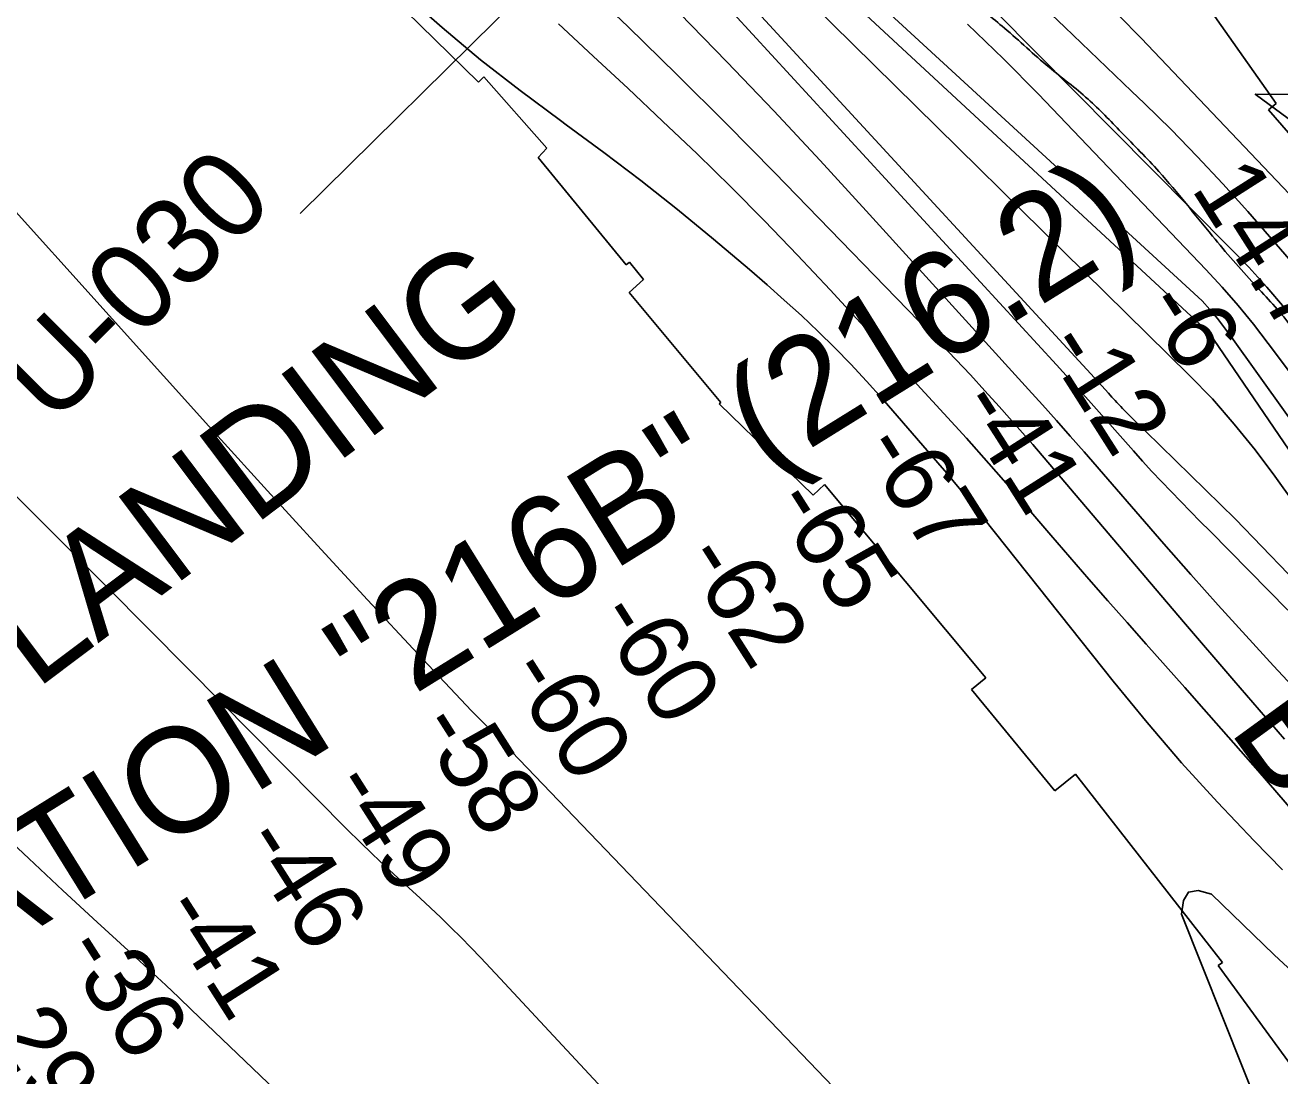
# Model space of a CAD drawing. Extents: x 3329297 to 3367176, y 649250 to 674653.
# Drawn here: x 3339953 to 3341150, y 667351 to 668353 of the extents above; entities that cross this region are included whole.
import ezdxf

# ---------------------------------------------------------------- set-up
doc = ezdxf.new("R2010")
doc.units = 0
for name, color, linetype in [('V-CHAN-NAID', 7, 'Continuous'), ('V-RIVR-EDGE', 7, 'Continuous'), ('V-RIVR-RANG', 7, 'Continuous'), ('V-RIVR-RANG-IDEN', 7, 'Continuous'), ('V-RRAP-RVMT', 7, 'Continuous'), ('V-RRAP-RVMT-IDEN', 7, 'Continuous'), ('V-TOPO-DPTH', 7, 'Continuous'), ('V-TOPO-GNAM-IDEN', 7, 'Continuous'), ('V-TOPO-MAJR', 7, 'Continuous'), ('V-TOPO-MINR', 7, 'Continuous'), ('V-TOPO-WATR', 7, 'Continuous')]:
    doc.layers.add(name, color=color, linetype=linetype)

msp = doc.modelspace()

# ---------------------------------------------------------------- linework, layer by layer
at = {"layer": 'V-CHAN-NAID'}
msp.add_lwpolyline([(3341203.1, 668286.4), (3341126.6, 668286.9), (3341188.2, 668241.5)], dxfattribs=at)
at = {"layer": 'V-RIVR-EDGE'}
msp.add_spline([(3342816.4, 664076.7), (3342812.8, 664100.7), (3342811.2, 664114.7), (3342810.5, 664125.2), (3342811.7, 664129.4), (3342815.9, 664131.4), (3342822.1, 664131), (3342827.6, 664133.7), (3342828, 664138.7), (3342825.7, 664163.5), (3342823, 664169.3), (3342818, 664185.3), (3342816.5, 664200), (3342816.9, 664208.9), (3342818.1, 664220.9), (3342817.3, 664227.1), (3342814.7, 664243.4), (3342809.3, 664257.4), (3342808.5, 664264), (3342808.9, 664272.5), (3342814.8, 664296.2), (3342814.8, 664305.5), (3342810.6, 664319.5), (3342799.8, 664338.9), (3342790.9, 664350.1), (3342779.7, 664360.3), (3342778.5, 664365.3), (3342779.3, 664369.2), (3342779.7, 664370.7), (3342785.9, 664376.9), (3342798.3, 664388.1), (3342804.2, 664396.3), (3342807.7, 664410.2), (3342807.3, 664416.8), (3342805, 664421.5), (3342805, 664424.2), (3342805.1, 664435), (3342805.5, 664451.3), (3342803.6, 664468.4), (3342800.1, 664485.5), (3342800.2, 664492.1), (3342800.6, 664495.9), (3342805.6, 664499.4), (3342810.3, 664507.2), (3342811.5, 664513.7), (3342812.6, 664526.5), (3342808.8, 664554.1), (3342808.5, 664564.6), (3342812, 664571.5), (3342819.8, 664577.7), (3342825.2, 664588.6), (3342825.6, 664596.7), (3342825.3, 664604.1), (3342821.4, 664610.7), (3342817.5, 664623.9), (3342808.6, 664632), (3342807.5, 664639), (3342807.5, 664645.6), (3342805.6, 664651), (3342795.5, 664667.7), (3342786.3, 664683.3), (3342782.8, 664682.1), (3342779.3, 664685.6), (3342772.4, 664698.8), (3342765, 664705.8), (3342757.7, 664715.1), (3342755, 664721), (3342755, 664725.2), (3342756.9, 664729.5), (3342762.4, 664734.9), (3342763.2, 664745.8), (3342759.3, 664768.7), (3342756.7, 664780.7), (3342750.5, 664796.2), (3342738.9, 664818.3), (3342728.9, 664839.3), (3342718.8, 664850.6), (3342704.5, 664870.4), (3342673.2, 664906.9), (3342667, 664917), (3342662.4, 664928.7), (3342645.8, 664948.1), (3342638.8, 664957.4), (3342632.6, 664969.9), (3342630.7, 664978), (3342626.9, 664985), (3342614.9, 664996.7), (3342611.4, 664999.4), (3342609.8, 665001.3), (3342609.9, 665006.4), (3342606.8, 665010.2), (3342597.9, 665020.4), (3342593.2, 665025.4), (3342592.5, 665033.2), (3342590.9, 665044.4), (3342589.4, 665054.5), (3342588.3, 665065.4), (3342586, 665077), (3342585.2, 665086.7), (3342585.3, 665096.4), (3342584.9, 665101), (3342582.9, 665104.2), (3342580.2, 665109.6), (3342577.2, 665117), (3342577.2, 665122.8), (3342577.2, 665131.7), (3342577.2, 665142.6), (3342577.3, 665154.2), (3342576.1, 665167.8), (3342572.7, 665193), (3342566.9, 665215.1), (3342563.5, 665229.5), (3342558.9, 665239.9), (3342557.3, 665244.2), (3342555.4, 665255.5), (3342553.1, 665268.7), (3342549.3, 665284.6), (3342541.6, 665307.1), (3342537.3, 665321.8), (3342532, 665340.1), (3342533.5, 665343.6), (3342533.5, 665349.8), (3342527, 665368.4), (3342525.5, 665379.6), (3342523.5, 665388.2), (3342518.1, 665403.7), (3342515.5, 665416.1), (3342514.3, 665430.9), (3342508.6, 665450.6), (3342503.2, 665470.8), (3342492.4, 665490.6), (3342491.6, 665499.2), (3342490.9, 665508.5), (3342486.3, 665532.9), (3342483.6, 665545.3), (3342477.8, 665557.8), (3342475.9, 665580.3), (3342474.8, 665594.2), (3342470.2, 665605.5), (3342467.9, 665614.4), (3342467.1, 665629.5), (3342466.4, 665643.5), (3342466.8, 665662.1), (3342467.3, 665679.6), (3342463.4, 665695.5), (3342454.9, 665713.7), (3342445.7, 665732.3), (3342448.4, 665735.4), (3342449.6, 665735.1), (3342454.6, 665728.8), (3342456.1, 665730.4), (3342456.1, 665730.8), (3342455.4, 665734.7), (3342442.2, 665751), (3342428.7, 665771.6), (3342413.6, 665800.7), (3342398.6, 665832.5), (3342380.5, 665869.4), (3342358.9, 665914.1), (3342350, 665938.5), (3342337.3, 665963.4), (3342312.2, 666021.6), (3342297.2, 666058.5), (3342281.7, 666092.6), (3342274.8, 666112.4), (3342267.5, 666136.1), (3342262.9, 666166), (3342261.4, 666190.8), (3342261.4, 666198.6), (3342257.6, 666197.8), (3342255.2, 666199.7), (3342252.9, 666205.2), (3342252.6, 666212.5), (3342252.6, 666219.1), (3342250.3, 666232.7), (3342241.8, 666258.3), (3342236.1, 666285.9), (3342231.8, 666289), (3342227.6, 666291.7), (3342219, 666302.6), (3342218.7, 666306.9), (3342219.1, 666312.3), (3342210.2, 666314.2), (3342205.1, 666318.9), (3342204, 666324.3), (3342204, 666330.2), (3342202.1, 666339.1), (3342191.6, 666356.6), (3342180, 666369), (3342175.4, 666377.5), (3342165, 666397), (3342154.6, 666421.8), (3342139.9, 666463.3), (3342130.7, 666487.8), (3342123, 666506.4), (3342111.8, 666527.4), (3342098.7, 666554.2), (3342094.8, 666565.8), (3342092.5, 666581.7), (3342088.7, 666594.5), (3342085.2, 666612.8), (3342082.2, 666622.1), (3342072.9, 666631.8), (3342063.2, 666645.4), (3342057.4, 666657.8), (3342049.7, 666678), (3342048.2, 666693.1), (3342050.2, 666696.6), (3342051, 666704.4), (3342046.7, 666709), (3342039.4, 666716.8), (3342032.4, 666729.2), (3342015.8, 666761.1), (3342003.1, 666780.9), (3341996.1, 666786.3), (3341994.9, 666792.6), (3341992.6, 666796.4), (3341983, 666812), (3341967.1, 666835.3), (3341953.6, 666848.9), (3341946.6, 666857.4), (3341940.5, 666867.9), (3341935.8, 666874.1), (3341919.2, 666884.3), (3341915.7, 666890.1), (3341911.4, 666900.2), (3341899.8, 666913.8), (3341894.8, 666921.2), (3341889, 666931.6), (3341869.3, 666956.9), (3341855, 666974.8), (3341848.8, 666978.7), (3341839.5, 666986.8), (3341829.1, 667000.4), (3341821.8, 667015.2), (3341819.1, 667024.9), (3341817.1, 667031.1), (3341806.3, 667038.9), (3341788.1, 667056.8), (3341778.5, 667070), (3341769.6, 667076.2), (3341763, 667079.7), (3341756, 667089), (3341748.3, 667099.5), (3341738.6, 667112.3), (3341730.9, 667120.1), (3341719.3, 667133.7), (3341714.7, 667143), (3341706.5, 667156.6), (3341694.9, 667171.8), (3341682.2, 667199), (3341673.7, 667217.2), (3341665.7, 667244.8), (3341658.4, 667270.8), (3341654.5, 667280.9), (3341646.8, 667297.6), (3341633.7, 667325.5), (3341621.3, 667347.3), (3341603.9, 667370.6), (3341601.6, 667379.1), (3341595.1, 667392.3), (3341586.6, 667412.5), (3341578.1, 667435.8), (3341568.4, 667448.2), (3341554.1, 667467.6), (3341537.5, 667492.5), (3341516.7, 667524), (3341476.1, 667581.9), (3341429.7, 667650.2), (3341398, 667697.2), (3341371, 667737.2), (3341354.8, 667763.6), (3341343.5, 667778.4), (3341338.9, 667782.3), (3341332.3, 667790.1), (3341325.4, 667806), (3341317.7, 667814.2), (3341305.3, 667827.4), (3341300.6, 667833.2), (3341282.9, 667869.7), (3341259.7, 667911.2), (3341224.6, 667969.5), (3341190.6, 668018.4), (3341159.7, 668067), (3341126, 668105.5), (3341085.8, 668151.7), (3341034.8, 668213.1), (3340998.8, 668250.8), (3340967.1, 668282.3), (3340929.9, 668312.7), (3340887.4, 668350), (3340852.5, 668378), (3340818.1, 668406), (3340783.6, 668439.1), (3340747.7, 668476), (3340722.9, 668504.4), (3340704.4, 668525.7), (3340693.9, 668537), (3340680.7, 668543.2), (3340672.6, 668546.8), (3340664.5, 668552.6), (3340650.9, 668563.5), (3340645.9, 668568.9), (3340640.9, 668576.7), (3340634.7, 668584.1), (3340619.6, 668601.6), (3340609.5, 668604.7), (3340603.7, 668609), (3340599.1, 668614.4), (3340595.6, 668621), (3340589.4, 668627.2), (3340567.8, 668645.9), (3340550, 668659.1), (3340496.9, 668702.7), (3340430.8, 668760.6), (3340383.9, 668798.8), (3340346.8, 668824.5), (3340317, 668845.1), (3340289.9, 668863.4), (3340255.4, 668891.8), (3340209.4, 668936.1), (3340181.1, 668962.9), (3340159.1, 668977.3), (3340134.3, 668996.4), (3340120.7, 669009.2), (3340113.4, 669017.8), (3340109.9, 669023.6), (3340107.6, 669025.9), (3340099.8, 669026.7), (3340094.4, 669027.9), (3340089.4, 669030.2), (3340085.1, 669036.5), (3340084.8, 669043), (3340082.1, 669046.2), (3340066.2, 669059), (3340051.1, 669071.4), (3340041.8, 669077.7), (3339987.6, 669116.2), (3339929.5, 669149.3), (3339882.3, 669177.3), (3339823.8, 669212), (3339768.8, 669245.9), (3339704.9, 669289.5), (3339659.6, 669320.6), (3339614, 669359.5), (3339576, 669382.9), (3339562.9, 669393), (3339559.4, 669394.5), (3339555.9, 669394.2), (3339553.2, 669389.9), (3339550.8, 669388.7), (3339546.2, 669392.2), (3339540.4, 669395.4), (3339537.3, 669393), (3339533, 669392.7), (3339518.7, 669398.1), (3339507.8, 669404.7), (3339498.9, 669411.4), (3339490, 669411.4), (3339486.5, 669416), (3339483.4, 669417.6), (3339473.4, 669420.7), (3339460.6, 669427.7), (3339447.8, 669435.5), (3339435.4, 669443.3), (3339423.8, 669453.4), (3339413.4, 669464.7), (3339407.9, 669471.3), (3339393.6, 669479.5), (3339378.1, 669489.2), (3339357.6, 669502.4), (3339355.7, 669504.8), (3339358.4, 669506.3), (3339359.6, 669509.4), (3339359.2, 669511), (3339356.5, 669515.3), (3339347.2, 669516.8), (3339341.3, 669512.6), (3339338.2, 669513.4), (3339320.8, 669525.8), (3339311.2, 669534.8), (3339296.1, 669548.8), (3339293.3, 669550.3), (3339286.4, 669549.2), (3339280.9, 669546.5), (3339277.1, 669546.5), (3339268.1, 669550), (3339250.7, 669559.7), (3339229, 669575.7), (3339210.8, 669587), (3339202.3, 669595.1), (3339200.4, 669599.4), (3339200, 669604.8), (3339198.1, 669611), (3339183, 669622.7), (3339166.4, 669632.4)], degree=3, dxfattribs=at)
at = {"layer": 'V-RIVR-RANG'}
msp.add_line((3341169.4, 669114.2), (3340215.5, 668173.1), dxfattribs=at)
at = {"layer": 'V-RRAP-RVMT'}
for p, q in [((3340297.9, 668384.3), (3340385.5, 668298.4)), ((3341146.5, 668278.1), (3341084.1, 668366.6)), ((3340385.5, 668298.4), (3340390.9, 668303.4)), ((3340390.9, 668303.4), (3340450.9, 668235.5)), ((3341139.4, 668272.1), (3341146.5, 668278.1)), ((3341224.3, 668173.5), (3341139.4, 668272.1)), ((3340450.9, 668235.5), (3340442.5, 668226.5)), ((3340442.5, 668226.5), (3340526.4, 668124.2)), ((3340526.4, 668124.2), (3340529.7, 668126.9)), ((3340529.7, 668126.9), (3340543.2, 668110.2)), ((3340543.2, 668110.2), (3340529.4, 668097.9)), ((3340529.4, 668097.9), (3340616.7, 667993.1)), ((3340616.7, 667993.1), (3340615.3, 667991.8)), ((3340615.3, 667991.8), (3340704.9, 667904.5)), ((3340704.9, 667904.5), (3340715.7, 667914.8)), ((3340715.7, 667914.8), (3340869.7, 667730.2)), ((3340869.7, 667730.2), (3340856.1, 667719.2)), ((3340856.1, 667719.2), (3340935.6, 667622.6)), ((3340935.6, 667622.6), (3340955.1, 667638.6)), ((3340955.1, 667638.6), (3341095.3, 667459)), ((3341095.3, 667459), (3341091.3, 667456.1)), ((3341091.3, 667456.1), (3341167.1, 667352))]:
    msp.add_line(p, q, dxfattribs=at)
at = {"layer": 'V-TOPO-DPTH'}
for points in [[(3341163.7, 667897), (3341145.4, 667922.7), (3341126.4, 667947.9), (3341106.5, 667972.4), (3341086, 667996.4), (3341063.9, 668018.6), (3340301.5, 668769.4)], [(3341163.7, 667897), (3341145.4, 667922.7), (3341126.4, 667947.9), (3341106.5, 667972.4), (3341086, 667996.4), (3341063.9, 668018.6), (3340301.5, 668769.4)], [(3340336.2, 668769.9), (3341076.1, 668089.9), (3341083.4, 668081.6), (3341090.6, 668073.1), (3341097.4, 668064.3), (3341104.1, 668055.4), (3341257.6, 667840.6)], [(3341257.6, 667840.6), (3341104.1, 668055.4), (3341097.4, 668064.3), (3341090.6, 668073.1), (3341083.4, 668081.6), (3341076.1, 668089.9), (3340336.2, 668769.9)], [(3340520.1, 668482.6), (3340936.9, 668028.8), (3340952.2, 668012), (3340967.5, 667995.1), (3340982.7, 667978.1), (3340997.8, 667961.1), (3341010.4, 667946.8), (3341019.2, 667936.9), (3341028.1, 667927.2), (3341037.2, 667917.5), (3341046.4, 667908), (3341055.7, 667898.5), (3341064.9, 667889.1), (3341074.2, 667879.6), (3341083.5, 667870.2), (3341157.8, 667794.8)], [(3341157.8, 667794.8), (3341083.5, 667870.2), (3341074.2, 667879.6), (3341064.9, 667889.1), (3341055.7, 667898.5), (3341046.4, 667908), (3341037.2, 667917.5), (3341028.1, 667927.2), (3341019.2, 667936.9), (3341010.4, 667946.8), (3340997.8, 667961.1), (3340982.7, 667978.1), (3340967.5, 667995.1), (3340952.2, 668012), (3340936.9, 668028.8), (3340520.1, 668482.6)], [(3340805.6, 668440), (3341102.5, 668140.5), (3341120.4, 668121.9), (3341137.8, 668102.8), (3341154.5, 668083.2)], [(3341154.4, 667671.8), (3341106.2, 667727.8), (3341058.2, 667783.8), (3340914.5, 667952.8), (3340912, 667955.6), (3340909.6, 667958.4), (3340907.2, 667961.2), (3340904.7, 667964), (3340882.4, 667989), (3340868.7, 668004.2), (3340854.9, 668019.2), (3340840.9, 668034.1), (3340826.7, 668048.9), (3340668, 668212.2), (3340621.8, 668259.1), (3340575.2, 668305.6), (3340528, 668351.4), (3340480.4, 668396.9)], [(3340480.4, 668396.9), (3340528, 668351.4), (3340575.2, 668305.6), (3340621.8, 668259.1), (3340668, 668212.2), (3340826.7, 668048.9), (3340840.9, 668034.1), (3340854.9, 668019.2), (3340868.7, 668004.2), (3340882.4, 667989), (3340904.7, 667964), (3340907.2, 667961.2), (3340909.6, 667958.4), (3340912, 667955.6), (3340914.5, 667952.8), (3341058.2, 667783.8), (3341106.2, 667727.8), (3341154.4, 667671.8)], [(3340577.3, 668364.3), (3340622.5, 668317.8), (3340667.3, 668271), (3340711.5, 668223.6), (3340755.4, 668175.9), (3340910.3, 668005.5), (3340923.7, 667990.7), (3340937, 667975.8), (3340950.2, 667960.8), (3340963.4, 667945.8), (3341039.5, 667858.2), (3341065.3, 667828.8), (3341091.3, 667799.6), (3341117.6, 667770.6), (3341144.1, 667741.8), (3341170.8, 667713.1)], [(3340577.3, 668364.3), (3340622.5, 668317.8), (3340667.3, 668271), (3340711.5, 668223.6), (3340755.4, 668175.9), (3340910.3, 668005.5), (3340923.7, 667990.7), (3340937, 667975.8), (3340950.2, 667960.8), (3340963.4, 667945.8), (3341039.5, 667858.2), (3341065.3, 667828.8), (3341091.3, 667799.6), (3341117.6, 667770.6), (3341144.1, 667741.8), (3341170.8, 667713.1)], [(3339924.2, 667588.4), (3339956.6, 667557.9), (3339989.1, 667527.5), (3340021.8, 667497.4), (3340062.5, 667460.1), (3340074.9, 667448.6), (3340087.3, 667437.1), (3340099.7, 667425.5), (3340112, 667413.8), (3340177.4, 667351.1), (3340200.5, 667328.8)], [(3340200.5, 667328.8), (3340177.4, 667351.1), (3340112, 667413.8), (3340099.7, 667425.5), (3340087.3, 667437.1), (3340074.9, 667448.6), (3340062.5, 667460.1), (3340021.8, 667497.4), (3339989.1, 667527.5), (3339956.6, 667557.9), (3339924.2, 667588.4)]]:
    msp.add_lwpolyline(points, dxfattribs=at)
at = {"layer": 'V-TOPO-MAJR'}
for points in [[(3341172.9, 667591), (3341129.5, 667641.8), (3341077.7, 667700.5), (3341059.4, 667721.2), (3341041.1, 667741.9), (3341022.7, 667762.5), (3341004.3, 667783.1), (3340986, 667803.8), (3340967.8, 667824.5), (3340949.7, 667845.4), (3340931.7, 667866.4), (3340914.5, 667886.6), (3340893.6, 667910.8), (3340872.5, 667934.9), (3340851.2, 667958.8), (3340829.6, 667982.5), (3340721, 668100.5), (3340690, 668133.6), (3340658.6, 668166.2), (3340626.6, 668198.3), (3340594.1, 668230), (3340561.3, 668261.2), (3340528.3, 668292.4), (3340495.2, 668323.4), (3340462, 668354.2)], [(3339875.8, 667971.6), (3339953.8, 667894.4), (3340031.4, 667816.8), (3340108.8, 667739), (3340260.7, 667585.5), (3340272.5, 667573.8), (3340284.4, 667562.2), (3340296.5, 667550.8), (3340308.7, 667539.5), (3340330, 667520.2), (3340340, 667511), (3340349.8, 667501.7), (3340359.4, 667492.3), (3340369, 667482.7), (3340378.4, 667473.1), (3340387.8, 667463.3), (3340397.1, 667453.5), (3340406.3, 667443.7), (3340508, 667334.3)]]:
    msp.add_lwpolyline(points, dxfattribs=at)
at = {"layer": 'V-TOPO-MINR'}
for points in [[(3341163.7, 667897), (3341145.4, 667922.7), (3341126.4, 667947.9), (3341106.5, 667972.4), (3341086, 667996.4), (3341063.9, 668018.6), (3340301.5, 668769.4)], [(3342189.2, 666175.3), (3342141.2, 666288), (3342040.7, 666518.3), (3342033.2, 666534.9), (3342025.4, 666551.3), (3342017.1, 666567.5), (3342008.6, 666583.5), (3341936.9, 666713.7), (3341891.8, 666794.4), (3341846, 666874.7), (3341799.1, 666954.3), (3341751.5, 667033.6), (3341573.1, 667326.3), (3341567.4, 667335.6), (3341561.7, 667344.8), (3341556, 667353.9), (3341550.2, 667363.1), (3341507.3, 667430.7), (3341479.8, 667473.5), (3341452.1, 667516.1), (3341423.9, 667558.5), (3341395.5, 667600.6), (3341082.7, 668059.4), (3340316.2, 668769.4)], [(3341158, 667829.4), (3341107.7, 667881.6), (3341007.6, 667979.6), (3341005.8, 667981.5), (3341003.9, 667983.4), (3341002, 667985.2), (3341000.1, 667987.1), (3340998.3, 667989), (3340996.4, 667990.9), (3340994.6, 667992.8), (3340992.9, 667994.8), (3340989.9, 667998.1), (3340986.7, 668001.7), (3340983.5, 668005.3), (3340980.2, 668008.9), (3340977, 668012.4), (3340401.4, 668636.9)], [(3341157.8, 667794.8), (3341083.5, 667870.2), (3341074.2, 667879.6), (3341064.9, 667889.1), (3341055.7, 667898.5), (3341046.4, 667908), (3341037.2, 667917.5), (3341028.1, 667927.2), (3341019.2, 667936.9), (3341010.4, 667946.8), (3340997.8, 667961.1), (3340982.7, 667978.1), (3340967.5, 667995.1), (3340952.2, 668012), (3340936.9, 668028.8), (3340520.1, 668482.6)], [(3341154.5, 668083.2), (3341137.8, 668102.8), (3341120.4, 668121.9), (3341102.5, 668140.5), (3340805.6, 668440)], [(3341165.4, 668185.3), (3341017.8, 668340.3), (3340953.9, 668405.7)], [(3341154.4, 667671.8), (3341106.2, 667727.8), (3341058.2, 667783.8), (3340914.5, 667952.8), (3340912, 667955.6), (3340909.6, 667958.4), (3340907.2, 667961.2), (3340904.7, 667964), (3340882.4, 667989), (3340868.7, 668004.2), (3340854.9, 668019.2), (3340840.9, 668034.1), (3340826.7, 668048.9), (3340668, 668212.2), (3340621.8, 668259.1), (3340575.2, 668305.6), (3340528, 668351.4), (3340480.4, 668396.9)], [(3340315.1, 668382.3), (3340351, 668350.7), (3340387.6, 668319.9), (3340425.4, 668290.4), (3340463.8, 668261.8), (3340469.3, 668257.9), (3340505.1, 668231.5), (3340540.6, 668204.6), (3340575.4, 668176.9), (3340609.8, 668148.6), (3340644.1, 668119.7), (3340660.9, 668105.3), (3340677.4, 668090.7), (3340693.7, 668075.8), (3340709.8, 668060.7), (3340725.5, 668045.2), (3340740.9, 668029.5), (3340755.9, 668013.3), (3340770.6, 667996.9), (3340823.9, 667935.5), (3340832.5, 667925.4), (3340841.1, 667915.2), (3340849.6, 667904.9), (3340857.9, 667894.6), (3340991.2, 667727.2), (3341023.4, 667687.9), (3341056.4, 667649.3), (3341090.6, 667611.8), (3341125.6, 667574.9), (3341152.6, 667547.2)], [(3341158.9, 668129.7), (3341119.4, 668175), (3341095.6, 668201.6), (3341071.3, 668227.7), (3341046.3, 668253.2), (3341020.9, 668278.2), (3341008.7, 668289.8), (3340976.8, 668320.3), (3340945, 668350.8), (3340913.2, 668381.4)], [(3341170.8, 667713.1), (3341144.1, 667741.8), (3341117.6, 667770.6), (3341091.3, 667799.6), (3341065.3, 667828.8), (3341039.5, 667858.2), (3340963.4, 667945.8), (3340950.2, 667960.8), (3340937, 667975.8), (3340923.7, 667990.7), (3340910.3, 668005.5), (3340755.4, 668175.9), (3340711.5, 668223.6), (3340667.3, 668271), (3340622.5, 668317.8), (3340577.3, 668364.3)], [(3341199.4, 667968.7), (3341139.1, 668049.3), (3341124.9, 668067.6), (3341110.3, 668085.5), (3341095.1, 668102.8), (3341079.4, 668119.8), (3340919.9, 668287), (3340886.4, 668320.8), (3340852.1, 668353.7)], [(3339822.8, 668309.2), (3340137.1, 667960.7), (3340184.5, 667908.6), (3340232, 667856.6), (3340279.8, 667804.9), (3340327.8, 667753.4), (3340378.9, 667698.9), (3340402.3, 667675.7), (3340978.1, 667075.5), (3340990.5, 667058), (3341002.8, 667040.3), (3341014.7, 667022.4), (3341026.4, 667004.4), (3341038, 666986.3), (3341049.5, 666968.1), (3341061.1, 666950), (3341072.6, 666931.8), (3341106.5, 666878.1), (3341135, 666833.2), (3341163.6, 666788.2)], [(3339924.2, 667588.4), (3339956.6, 667557.9), (3339989.1, 667527.5), (3340021.8, 667497.4), (3340062.5, 667460.1), (3340074.9, 667448.6), (3340087.3, 667437.1), (3340099.7, 667425.5), (3340112, 667413.8), (3340177.4, 667351.1), (3340200.5, 667328.8)], [(3341173.8, 667209.9), (3341056.3, 667505.1), (3341058.1, 667517.9), (3341062.9, 667526.1), (3341072.3, 667527.4), (3341084.8, 667524), (3341114.7, 667495), (3341144.7, 667466.2), (3341175.1, 667437.8)]]:
    msp.add_lwpolyline(points, dxfattribs=at)
at = {"layer": 'V-TOPO-WATR'}
msp.add_lwpolyline([(3341257.6, 667840.6), (3341104.1, 668055.4), (3341097.4, 668064.3), (3341090.6, 668073.1), (3341083.4, 668081.6), (3341076.1, 668089.9), (3340336.2, 668769.9)], dxfattribs=at)

# ---------------------------------------------------------------- texts
at = {"layer": 'V-CHAN-NAID'}
msp.add_text('LONGWOOD PLANTATION "216B" (216.2)', height=100, rotation=31.8353, dxfattribs=at).set_placement((3338819.2, 666779.6))
at = {"layer": 'V-RIVR-RANG'}
for s, p in [('14.7', (3341064.7, 668197.2)), ('-6', (3341017.5, 668085.2)), ('-12', (3340923.5, 668046.8)), ('-41', (3340840.6, 667990.8)), ('-67', (3340748.4, 667949.3)), ('-65', (3340663.3, 667896.8)), ('-62', (3340578.3, 667844.2)), ('-60', (3340494.8, 667789.1)), ('-60', (3340410.3, 667735.5)), ('-58', (3340324.9, 667683.5)), ('-49', (3340242, 667627.5)), ('-46', (3340157.4, 667574.2)), ('-41', (3340080.4, 667508.9)), ('-36', (3339986.5, 667470.2)), ('-29', (3339902.5, 667416))]:
    msp.add_text(s, height=67, rotation=302.516, dxfattribs=at).set_placement(p)
at = {"layer": 'V-RIVR-RANG-IDEN'}
msp.add_text('U-030', height=83, rotation=45.0116, dxfattribs=at).set_placement((3339979.4, 667969.5))
at = {"layer": 'V-RRAP-RVMT-IDEN'}
msp.add_text('BEND', height=100, rotation=306.0152, dxfattribs=at).set_placement((3341100.3, 667681.2))
at = {"layer": 'V-TOPO-GNAM-IDEN'}
msp.add_text('LONGWOOD LANDING', height=100, rotation=36.9663, dxfattribs=at).set_placement((3339286.5, 667209))

doc.saveas('drawing.dxf')
